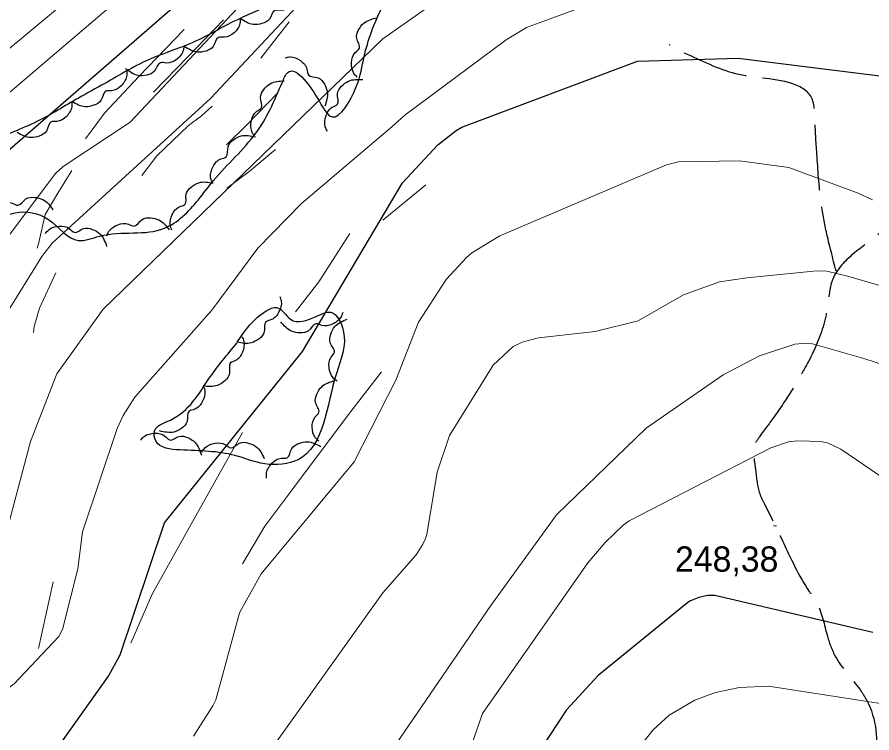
# Model space of a CAD drawing. Extents: x 480269 to 484877, y 4383588 to 4386804.
# Drawn here: x 483563.2 to 483859, y 4386087.1 to 4386334.7 of the extents above; entities that cross this region are included whole.
import ezdxf

# ---------------------------------------------------------------- set-up
doc = ezdxf.new("R2010")
doc.units = 0
doc.header["$LTSCALE"] = 3.8
doc.linetypes.add('LONG_DASHED', pattern=[7.5, 6, -1.5])
for name, color, linetype, lineweight in [('27', 7, 'Continuous', 25), ('38', 7, 'Continuous', 25), ('51', 7, 'Continuous', 13), ('7', 7, 'Continuous', 13), ('8', 7, 'Continuous', 25), ('9', 7, 'Continuous', 13)]:
    doc.layers.add(name, color=color, linetype=linetype, lineweight=lineweight)

msp = doc.modelspace()

# ---------------------------------------------------------------- linework, layer by layer
at = {"layer": '27'}
for points in [[(483471.95, 4386194.86), (483469.67, 4386214.21), (483472.52, 4386227.55), (483474.19, 4386241.33), (483465.32, 4386241.5), (483458.33, 4386241.06), (483450.45, 4386256.31), (483450.84, 4386260.68), (483456.75, 4386276.9), (483466.13, 4386289.21), (483477.44, 4386279.82), (483489.86, 4386286.04), (483494.39, 4386293.4), (483497.33, 4386310.41), (483484.88, 4386314.12), (483474.28, 4386313.24), (483467.45, 4386324.04), (483477.58, 4386341.47), (483481.84, 4386351.15), (483485.16, 4386359.67), (483502.67, 4386373.19), (483518.14, 4386383.72), (483532.43, 4386396.05), (483554.3, 4386397.74), (483573.29, 4386393.95), (483585.86, 4386387.34), (483609.85, 4386386.01), (483624.59, 4386388.63), (483641.47, 4386388.32), (483660.2, 4386387.22), (483666.6, 4386386.73), (483688.6, 4386387.25), (483698.13, 4386386.22), (483689.47, 4386373.47), (483668.93, 4386351.54), (483655.18, 4386341.14), (483640.53, 4386334.36), (483622.6, 4386325.34), (483609.64, 4386320.39), (483593.52, 4386311.76), (483584.38, 4386306.69), (483569.96, 4386298.54), (483553.88, 4386291.27), (483536.55, 4386280.08), (483521.28, 4386271.21), (483507.45, 4386260.68), (483503.22, 4386251.96), (483502.23, 4386247.38), (483505.34, 4386235.56), (483515.9, 4386240.34), (483519.7, 4386242.33), (483538.59, 4386259.86), (483555.46, 4386264.41), (483562.52, 4386267.05), (483574, 4386264.66), (483584.43, 4386257.41), (483591.74, 4386258.94), (483614.17, 4386261.67), (483625.8, 4386271.41), (483631.16, 4386278.21), (483645.79, 4386294.54), (483654.97, 4386312.23), (483656.81, 4386315.53), (483667.08, 4386306.72), (483672.15, 4386300.18), (483680.54, 4386310.53), (483683.26, 4386321.02), (483689.54, 4386338.18), (483702.41, 4386354.33), (483718.31, 4386362.24), (483738.82, 4386372.04), (483744, 4386374.96), (483753.51, 4386385.63), (483766.35, 4386395.26), (483789.76, 4386404.73), (483792.36, 4386408.78)], [(483660.06, 4386343.42), (483659.89, 4386341.65), (483657.75, 4386338.51), (483654.37, 4386337.05), (483652.31, 4386337.05), (483650.46, 4386334.01), (483647.9, 4386332.49), (483644.89, 4386332.16), (483640.39, 4386334.24)], [(483640.4, 4386334.24), (483640.27, 4386332.46), (483638.23, 4386329.27), (483634.88, 4386327.72), (483632.82, 4386327.67), (483631.06, 4386324.58), (483628.53, 4386322.98), (483625.54, 4386322.58), (483620.98, 4386324.54)], [(483680.88, 4386313.91), (483679.72, 4386315.25), (483678.91, 4386318.95), (483680.19, 4386322.42), (483681.6, 4386323.91), (483680.67, 4386327.34), (483681.33, 4386330.25), (483683.16, 4386332.65), (483687.77, 4386334.49)], [(483620.88, 4386324.78), (483620.6, 4386323.03), (483618.27, 4386320.03), (483614.79, 4386318.79), (483612.74, 4386318.93), (483610.7, 4386316.02), (483608.04, 4386314.66), (483605.02, 4386314.53), (483600.66, 4386316.9)], [(483655.91, 4386320.67), (483657.66, 4386320.94), (483661.23, 4386319.64), (483663.47, 4386316.71), (483663.98, 4386314.72), (483667.38, 4386313.67), (483669.49, 4386311.56), (483670.54, 4386308.73), (483669.62, 4386303.85)], [(483601.09, 4386315.95), (483601.04, 4386314.18), (483599.13, 4386310.9), (483595.85, 4386309.21), (483593.8, 4386309.07), (483592.17, 4386305.91), (483589.72, 4386304.21), (483586.74, 4386303.68), (483582.1, 4386305.45)], [(483645.29, 4386293.61), (483644.37, 4386295.14), (483644.22, 4386298.93), (483646.07, 4386302.12), (483647.72, 4386303.34), (483647.4, 4386306.88), (483648.55, 4386309.63), (483650.78, 4386311.68), (483655.63, 4386312.69)], [(483670.58, 4386295.18), (483669.82, 4386296.78), (483670.06, 4386300.57), (483672.23, 4386303.55), (483674, 4386304.6), (483674.04, 4386308.16), (483675.46, 4386310.78), (483677.89, 4386312.59), (483682.82, 4386313.1)], [(483582.12, 4386305.42), (483582.09, 4386303.65), (483580.21, 4386300.35), (483576.94, 4386298.63), (483574.89, 4386298.47), (483573.29, 4386295.3), (483570.85, 4386293.57), (483567.88, 4386293.02), (483563.23, 4386294.74)], [(483630.61, 4386277.63), (483630.13, 4386279.34), (483630.98, 4386283.04), (483633.62, 4386285.63), (483635.53, 4386286.37), (483636.16, 4386289.87), (483638, 4386292.22), (483640.68, 4386293.6), (483645.63, 4386293.29)], [(483616.72, 4386260.97), (483616.15, 4386262.65), (483616.83, 4386266.38), (483619.33, 4386269.1), (483621.21, 4386269.93), (483621.67, 4386273.46), (483623.39, 4386275.89), (483626.01, 4386277.41), (483630.97, 4386277.33)], [(483553.93, 4386266.38), (483554.71, 4386267.98), (483557.81, 4386270.16), (483561.5, 4386270.34), (483563.42, 4386269.62), (483566.22, 4386271.81), (483569.15, 4386272.34), (483572.08, 4386271.59), (483575.57, 4386268.06)], [(483594.2, 4386258.99), (483594.95, 4386260.6), (483598, 4386262.85), (483601.69, 4386263.1), (483603.62, 4386262.42), (483606.38, 4386264.67), (483609.3, 4386265.26), (483612.24, 4386264.57), (483615.8, 4386261.11)], [(483572.91, 4386259.81), (483574.1, 4386261.12), (483577.68, 4386262.36), (483581.28, 4386261.5), (483582.92, 4386260.27), (483586.22, 4386261.59), (483589.19, 4386261.28), (483591.79, 4386259.74), (483594.15, 4386255.38)], [(483654.07, 4386238.1), (483654.57, 4386236.39), (483653.77, 4386232.69), (483651.17, 4386230.06), (483649.26, 4386229.3), (483648.69, 4386225.79), (483646.88, 4386223.41), (483644.21, 4386221.99), (483639.26, 4386222.24)], [(483639.27, 4386222.24), (483649.37, 4386233.06), (483652.97, 4386234.26), (483657.78, 4386230.18), (483666.67, 4386231.14), (483671.72, 4386232.58), (483676.04, 4386226.33), (483673.64, 4386211.42), (483660.42, 4386181.6), (483648.88, 4386180.16), (483638.55, 4386183.05), (483619.56, 4386184.97), (483611.15, 4386188.1), (483610.67, 4386191.46), (483616.2, 4386195.31), (483629.66, 4386209.74), (483639.27, 4386222)], [(483675.86, 4386232.54), (483675.2, 4386230.89), (483672.27, 4386228.48), (483668.6, 4386228.04), (483666.63, 4386228.62), (483664, 4386226.22), (483661.11, 4386225.48), (483658.14, 4386226.02), (483654.4, 4386229.28)], [(483673.87, 4386208.79), (483672.51, 4386209.92), (483671.12, 4386213.45), (483671.82, 4386217.08), (483672.98, 4386218.77), (483671.51, 4386222.01), (483671.7, 4386224.99), (483673.13, 4386227.66), (483677.38, 4386230.2)], [(483640.98, 4386224.18), (483641.62, 4386222.52), (483641.14, 4386218.76), (483638.78, 4386215.92), (483636.94, 4386215), (483636.67, 4386211.45), (483635.07, 4386208.93), (483632.54, 4386207.28), (483627.58, 4386207.1)], [(483667.62, 4386187.97), (483666.36, 4386189.22), (483665.29, 4386192.86), (483666.32, 4386196.41), (483667.62, 4386197.99), (483666.45, 4386201.35), (483666.9, 4386204.3), (483668.56, 4386206.83), (483673.02, 4386208.98)], [(483627.69, 4386207), (483628.15, 4386205.28), (483627.25, 4386201.6), (483624.58, 4386199.05), (483622.66, 4386198.33), (483621.99, 4386194.84), (483620.12, 4386192.51), (483617.42, 4386191.16), (483612.47, 4386191.53)], [(483605.87, 4386188.39), (483607.11, 4386189.65), (483610.74, 4386190.75), (483614.3, 4386189.75), (483615.89, 4386188.45), (483619.24, 4386189.65), (483622.19, 4386189.22), (483624.73, 4386187.58), (483626.92, 4386183.12)], [(483627.1, 4386184.25), (483628.16, 4386185.68), (483631.6, 4386187.27), (483635.26, 4386186.77), (483637.02, 4386185.71), (483640.17, 4386187.36), (483643.15, 4386187.35), (483645.9, 4386186.08), (483648.68, 4386181.98)], [(483649.5, 4386175.25), (483649.51, 4386177.03), (483651.35, 4386180.34), (483654.6, 4386182.1), (483656.64, 4386182.28), (483658.21, 4386185.48), (483660.63, 4386187.23), (483663.59, 4386187.82), (483668.27, 4386186.15)]]:
    msp.add_spline(points, degree=3, dxfattribs=at)
at = {"layer": '38', "linetype": 'LONG_DASHED'}
for points in [[(483846.65, 4386246.83), (483843.21, 4386260.41), (483841.38, 4386270.76), (483839.93, 4386287.4), (483839.22, 4386299.87), (483838.29, 4386306.39), (483820.95, 4386313.64), (483811.89, 4386315.09), (483794.1, 4386322.24), (483789.79, 4386324.47), (483788.94, 4386325.16)], [(483874.69, 4386277.47), (483866.24, 4386264.28), (483858.29, 4386257.24), (483849.3, 4386249.79), (483845.66, 4386244.6), (483843.81, 4386235.97), (483842.32, 4386228.47), (483836.57, 4386214.75), (483832.14, 4386207.07), (483825.38, 4386196.78), (483819.99, 4386189.43), (483818.24, 4386186.18), (483818.11, 4386182.63), (483818.73, 4386177.98), (483820.14, 4386169.86), (483821.64, 4386166.58), (483828.05, 4386153.47), (483837.31, 4386135.99), (483839.85, 4386132.1), (483843.56, 4386120.56), (483846.7, 4386112.88), (483855.38, 4386101.33), (483857.78, 4386097.14), (483858.46, 4386076.32), (483853.94, 4386070.77), (483845.75, 4386063.52), (483839.61, 4386053.82), (483837.34, 4386047.31), (483834.52, 4386030.3), (483832.12, 4386019.3), (483829.3, 4386014.37), (483823.27, 4386008.22), (483817.04, 4385999.14), (483812.16, 4385983.89), (483810.67, 4385969.66), (483807.82, 4385954.51), (483806.01, 4385946.05), (483804.98, 4385938.54), (483804.45, 4385926), (483804.51, 4385920.94)]]:
    msp.add_spline(points, degree=3, dxfattribs=at)
at = {"layer": '51'}
for p, q in [((483657.26, 4386333.02), (483647.51, 4386320.48)), ((483689.71, 4386264.44), (483704.64, 4386276.7)), ((483575.6, 4386139.36), (483570.6, 4386116.26))]:
    msp.add_line(p, q, dxfattribs=at)
for points in [[(483634.63, 4386333.78), (483622.27, 4386320.97), (483610.4, 4386308.73)], [(483620.97, 4386330.38), (483605.29, 4386314.18), (483593.41, 4386301.49), (483586.79, 4386292.58)], [(483653.41, 4386308.49), (483642.73, 4386297.51), (483635.62, 4386290.51)], [(483606.27, 4386279.93), (483611.5, 4386286.69), (483622.51, 4386297.24), (483627.02, 4386300.52), (483630.62, 4386303.88)], [(483652.63, 4386288.85), (483643.38, 4386281.16), (483635.74, 4386275.52)], [(483582.1, 4386281.61), (483577.3, 4386273.84), (483572.87, 4386266.42), (483570.63, 4386256.77), (483570.11, 4386254.73)], [(483659.5, 4386232.74), (483667.59, 4386243.13), (483678.3, 4386259.79)], [(483576.52, 4386246.26), (483570.88, 4386234.04), (483569.12, 4386227.63), (483568.78, 4386225.64)], [(483689.28, 4386211.96), (483677.55, 4386196.82), (483658.89, 4386171.93), (483648.92, 4386158.64), (483641.16, 4386145.52)], [(483602.53, 4386118.12), (483609.86, 4386135.04), (483621.75, 4386156.43), (483641.18, 4386191.03)]]:
    msp.add_lwpolyline(points, dxfattribs=at)
at = {"layer": '7'}
msp.add_line((483824.94, 4386158.66), (483825.94, 4386158.66), dxfattribs=at)
at = {"layer": '8'}
for points in [[(483731.11, 4386448.99), (483682.93, 4386413.95), (483626.49, 4386346.25), (483539.48, 4386270.63)], [(483576.64, 4386081.2), (483594.75, 4386106.67), (483598.79, 4386114.1), (483614.13, 4386159.8), (483661.87, 4386219.05), (483696.56, 4386277.34), (483708.79, 4386290.47), (483715.15, 4386295.47), (483717.06, 4386296.68), (483777.83, 4386319.5), (483812.73, 4386320.55), (483878.31, 4386312.32)], [(483859.33, 4386121.84), (483804.67, 4386134.64), (483802.05, 4386134.57), (483799.1, 4386133.94), (483796.24, 4386132.76), (483795.25, 4386132.14), (483764.2, 4386106.89), (483753.34, 4386095.07), (483741.77, 4386077.52)]]:
    msp.add_lwpolyline(points, dxfattribs=at)
at = {"layer": '9'}
for points in [[(483672.86, 4386449.13), (483583.28, 4386342.82), (483519.65, 4386290.06), (483514.63, 4386287.6), (483513.26, 4386287.25), (483512.71, 4386287.19), (483511.68, 4386287.22), (483511.03, 4386287.36), (483510.88, 4386287.43), (483510.75, 4386287.5), (483510.36, 4386287.85), (483510.07, 4386288.34), (483509.68, 4386289.4), (483509.42, 4386290.64), (483509.22, 4386293.96), (483509.74, 4386299.89), (483513.45, 4386315.65), (483524.91, 4386346.36), (483533.59, 4386384.79), (483535.38, 4386449.46)], [(483707.74, 4386449.05), (483651.15, 4386400.14), (483610.6, 4386351.36), (483516.73, 4386271.34)], [(483782.26, 4386448.87), (483777.89, 4386448.11), (483758, 4386439.89), (483711.09, 4386412.1), (483708.91, 4386410.07), (483684.45, 4386382.25), (483661.64, 4386361.59), (483602.29, 4386298.36), (483579.13, 4386283.04), (483576.49, 4386280.57), (483544.3, 4386237.91)], [(483881.57, 4386416.39), (483828.18, 4386416.24), (483805.3, 4386419.36), (483799.27, 4386419.28), (483782.53, 4386416.28), (483759.66, 4386415.03), (483757.32, 4386414.6), (483746.26, 4386411.08), (483718.4, 4386393.8), (483691.56, 4386372.2), (483630.09, 4386306.58), (483575.25, 4386256.53), (483571.68, 4386251.85), (483559.19, 4386231.59)], [(483534.48, 4386112.48), (483536.83, 4386113.51), (483544.28, 4386119.1), (483545.81, 4386120.58), (483552.33, 4386129.97), (483567.76, 4386187.85), (483576.94, 4386211.34), (483592.94, 4386233.7), (483689.74, 4386327.17), (483765.89, 4386380.66), (483779.49, 4386387.55), (483803.39, 4386392.9), (483813.67, 4386393.54), (483815.6, 4386393.47), (483832.51, 4386390.05), (483835.24, 4386389.24), (483848.8, 4386383.29), (483851.16, 4386382.71), (483866.73, 4386382.96)], [(483895.28, 4386344.62), (483855.28, 4386341.51), (483852.27, 4386342.08), (483829.94, 4386349.13), (483819.84, 4386350.55), (483785.89, 4386348.29), (483739.46, 4386331.14), (483732.38, 4386326.85), (483697.38, 4386300.81), (483692.86, 4386296.7), (483661.61, 4386270.28), (483646.52, 4386254.72), (483630.54, 4386233.35), (483603.89, 4386203.18), (483599.92, 4386196.83), (483597.74, 4386192.38), (483585.8, 4386156.66), (483584.12, 4386143.82), (483578.89, 4386122.81), (483577.59, 4386120.46), (483562.17, 4386104), (483553.34, 4386097.71), (483546.85, 4386094.28), (483506.14, 4386078.27)], [(483624.25, 4386085.99), (483630.95, 4386096.48), (483631.94, 4386098.51), (483639.95, 4386128.13), (483640.24, 4386128.88), (483647.65, 4386142.05), (483679.81, 4386180.88), (483694.22, 4386209.14), (483702.08, 4386229.19), (483711.65, 4386243.96), (483718.67, 4386251.53), (483720.48, 4386253.12), (483730.22, 4386259), (483787.92, 4386283.63), (483791.99, 4386284.63), (483813.18, 4386285.01), (483830.18, 4386282.66), (483854.17, 4386273.83), (483859.13, 4386271.47)], [(483643.97, 4386071.39), (483689.76, 4386135.57), (483701.25, 4386148.7), (483703.6, 4386152.36), (483704.51, 4386154.35), (483704.95, 4386155.69), (483708.57, 4386177.32), (483712.83, 4386189.96), (483727.85, 4386214.32), (483734.88, 4386220.75), (483737.89, 4386222.28), (483743.57, 4386223.75), (483763.24, 4386225.92), (483778.03, 4386229.6), (483793.72, 4386238.64), (483806.21, 4386243.09), (483815.69, 4386244.55), (483839.94, 4386246.98), (483843.39, 4386246.76), (483850.96, 4386244.96), (483861.21, 4386241.92)], [(483889.19, 4386205.91), (483856.16, 4386216.62), (483838.4, 4386221.63), (483834.93, 4386221.79), (483832.25, 4386221.52), (483820.1, 4386217.53), (483807.48, 4386210.9), (483780.9, 4386192.54), (483749.79, 4386162.46), (483727.12, 4386131.2), (483661.13, 4386034.7)], [(483705.55, 4386039.9), (483724.18, 4386093.84), (483760.71, 4386145.95), (483766.66, 4386152.97), (483772.88, 4386158.92), (483775, 4386160.4), (483824.02, 4386185.69), (483830.14, 4386187.74), (483830.62, 4386187.84), (483830.83, 4386187.91), (483833.35, 4386188.09), (483841.4, 4386187.9), (483843.82, 4386187.28), (483848.18, 4386185.25), (483866.66, 4386172.71)], [(483765.31, 4386065.68), (483783.32, 4386088.13), (483788.81, 4386093.16), (483797.72, 4386098.38), (483804.8, 4386101.07), (483813.2, 4386102.74), (483823.24, 4386103.26), (483893.19, 4386092.4), (483908.72, 4386085.15)]]:
    msp.add_lwpolyline(points, dxfattribs=at)

# ---------------------------------------------------------------- texts
at = {"layer": '7'}
msp.add_text('248,38', height=8.75, dxfattribs=at).set_placement((483790.83, 4386142.85))

doc.saveas('drawing.dxf')
